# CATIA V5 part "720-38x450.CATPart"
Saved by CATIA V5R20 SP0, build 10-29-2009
Part number: 720-38x450
Definition: NONE
Nomenclature: 720-38x450
Source: Unknown
Description: 720-38x450
Bounding box of the stored display mesh (mm): x 0 to 450, y -19 to 19, z -19 to 19
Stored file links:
  C:\Users\Utente\Desktop\IO LAVORO\3D X SITO CF\X SITO\720\720-38x450.CATPart
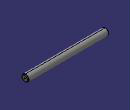
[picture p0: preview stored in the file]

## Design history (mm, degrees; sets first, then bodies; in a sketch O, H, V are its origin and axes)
Body1 "720-38x450" (main body)
  Solid1: solid without history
